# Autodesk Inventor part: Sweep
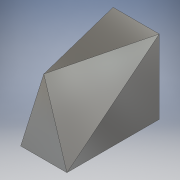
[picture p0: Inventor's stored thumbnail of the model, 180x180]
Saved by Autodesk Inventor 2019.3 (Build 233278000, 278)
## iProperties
Created: 2019-02
Part Number: Sweep
Material: Nickel-Copper Alloy 400
Document SubType Name: Modeling
Designer: Synergysoft
Density: 8.83 g/cm^3
Appearance: Chrome - Polished
Author: Synergysoft
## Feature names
1. Extrusion1
2. Sweep1
## Parameters: d0 = 25 mm, d3 = 0, d4 = 0, d5 = 0
